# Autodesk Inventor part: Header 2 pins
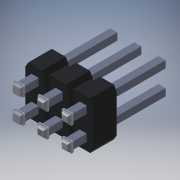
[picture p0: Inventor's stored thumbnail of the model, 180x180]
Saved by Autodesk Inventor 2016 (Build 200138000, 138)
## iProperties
Created: 2018-03
Part Number: Header 2 pins
Material: Générique
Document SubType Name: Modeling
Designer: Bruno
Density: 1 g/cm^3
Appearance: Par défaut
Author: Bruno
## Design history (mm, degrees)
feature "Composite1"
body "Srf1"
